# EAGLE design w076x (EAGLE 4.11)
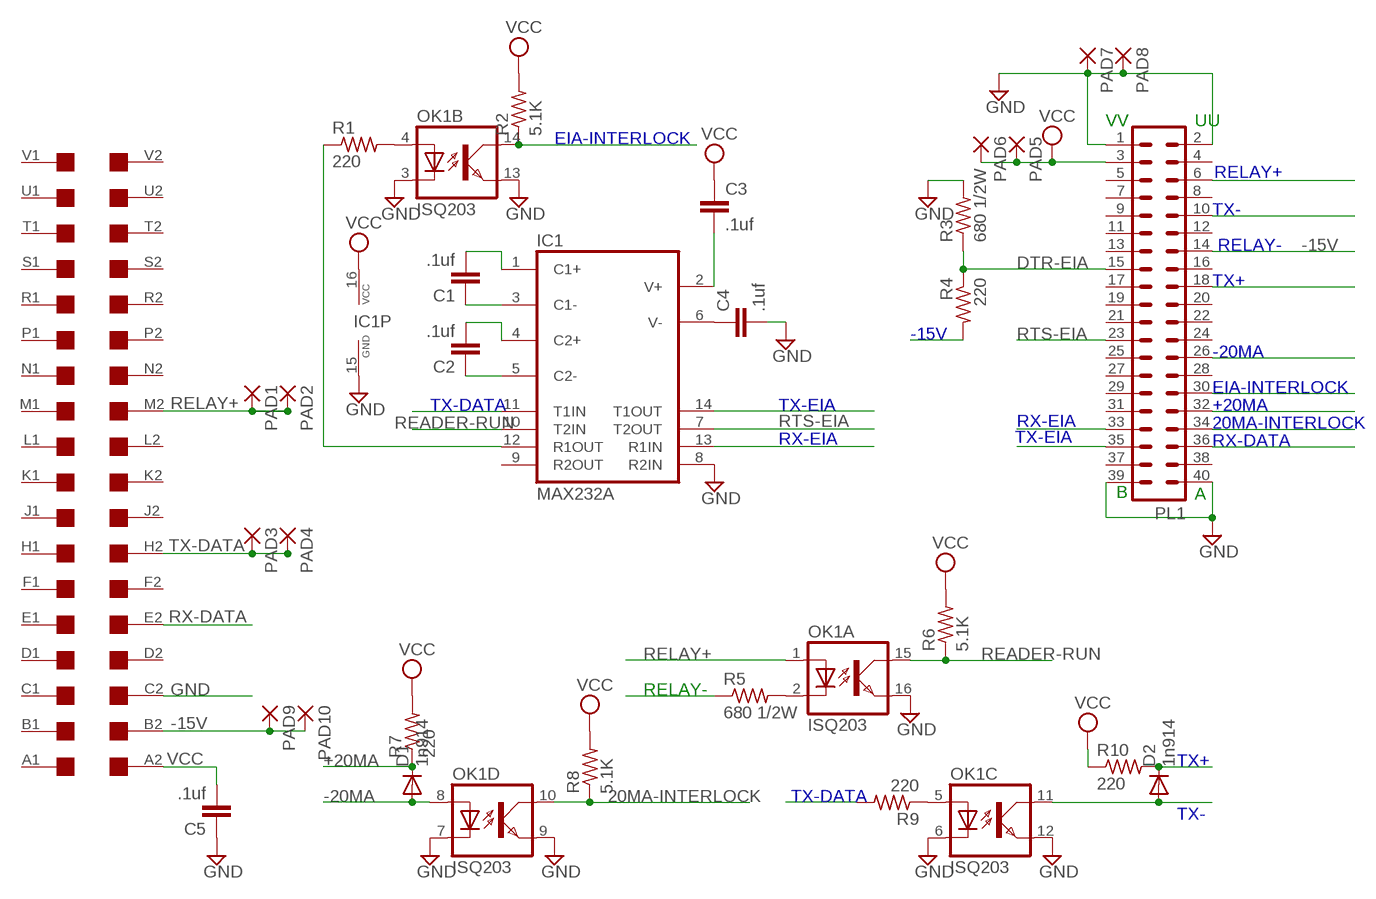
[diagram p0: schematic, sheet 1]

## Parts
C1  .1uf  C-EU050-025X075  [C050-025X075]
C2  .1uf  C-EU050-025X075  [C050-025X075]
C3  .1uf  C-EU050-025X075  [C050-025X075]
C4  .1uf  C-EU050-025X075  [C050-025X075]
C5  .1uf  C-EU050-025X075  [C050-025X075]
D1  1n914  1N4004  [DO41-10]
D2  1n914  1N4004  [DO41-10]
IC1  MAX232A  MAX232  [DIL16]
OK1  ISQ203  ILQ1  [DIL16]
PAD1  1,6/0,8  [1,6/0,8]
PAD2  1,6/0,8  [1,6/0,8]
PAD3  1,6/0,8  [1,6/0,8]
PAD4  1,6/0,8  [1,6/0,8]
PAD5  1,6/0,8  [1,6/0,8]
PAD6  1,6/0,8  [1,6/0,8]
PAD7  1,6/0,8  [1,6/0,8]
PAD8  1,6/0,8  [1,6/0,8]
PAD9  1,6/0,8  [1,6/0,8]
PAD10  1,6/0,8  [1,6/0,8]
PL1  40H  [40H]
R1  220  R-US_0207/10  [0207/10]
R2  5.1K  R-US_0207/10  [0207/10]
R3  680 1/2W  R-US_0207/12  [0207/12]
R4  220  R-US_0207/10  [0207/10]
R5  680 1/2W  R-US_0207/12  [0207/12]
R6  5.1K  R-US_0207/10  [0207/10]
R7  220  R-US_0207/10  [0207/10]
R8  5.1K  R-US_0207/10  [0207/10]
R9  220  R-US_0207/10  [0207/10]
R10  220  R-US_0207/10  [0207/10]
U$1  DEC-FLIPCHIP  [DEC-FLIPCHIP]

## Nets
20MA-INTERLOCK: OK1.10(D:COL) PL1.34 R8.1
+20MA: D1.C PL1.32 R7.1
-15V: PAD9.1(P) PAD10.1(P) PL1.14 R4.2 R5.1 U$1.B2
-20MA: D1.A OK1.8(D:A) PL1.26
DTR-EIA: PL1.15 R3.1 R4.1
EIA-INTERLOCK: OK1.14(B:COL) PL1.30 R2.1
GND: C4.2 C5.1 IC1.8(R2IN) IC1.15(GND) OK1.3(B:C) OK1.6(C:C) OK1.7(D:C) OK1.9(D:EMIT) OK1.12(C:EMIT) OK1.13(B:EMIT) OK1.16(A:EMIT) PAD7.1(P) PAD8.1(P) PL1.1 PL1.2 PL1.39 PL1.40 R3.2 U$1.C2
N$1: C2.1 IC1.5(C2-)
N$2: C2.2 IC1.4(C2+)
N$3: C1.2 IC1.1(C1+)
N$4: C1.1 IC1.3(C1-)
N$5: OK1.2(A:C) R5.2
N$8: IC1.12(R1OUT) R1.1
N$9: C3.2 IC1.2(V+)
N$10: C4.1 IC1.6(V-)
N$11: OK1.4(B:A) R1.2
N$15: OK1.5(C:A) R9.1
READER-RUN: IC1.10(T2IN) OK1.15(A:COL) R6.1
RELAY+: OK1.1(A:A) PAD1.1(P) PAD2.1(P) PL1.6 U$1.M2
RTS-EIA: IC1.7(T2OUT) PL1.23
RX-DATA: PL1.36 U$1.E2
RX-EIA: IC1.13(R1IN) PL1.33
TX+: D2.C PL1.18 R10.2
TX-: D2.A OK1.11(C:COL) PL1.10
TX-DATA: IC1.11(T1IN) PAD3.1(P) PAD4.1(P) R9.2 U$1.H2
TX-EIA: IC1.14(T1OUT) PL1.35
VCC: C3.1 C5.2 IC1.16(VCC) PAD5.1(P) PAD6.1(P) PL1.3 R2.2 R6.2 R7.2 R8.2 R10.1 U$1.A2
Unconnected: IC1.9(R2OUT) PL1.4 PL1.5 PL1.7 PL1.8 PL1.9 PL1.11 PL1.12 PL1.13 PL1.16 PL1.17 PL1.19 PL1.20 PL1.21 PL1.22 PL1.24 PL1.25 PL1.27 PL1.28 PL1.29 PL1.31 PL1.37 PL1.38 U$1.A1 U$1.B1 U$1.C1 U$1.D1 U$1.D2 U$1.E1 U$1.F1 U$1.F2 U$1.H1 U$1.J1 U$1.J2 U$1.K1 U$1.K2 U$1.L1 U$1.L2 U$1.M1 U$1.N1 U$1.N2 U$1.P1 U$1.P2 U$1.R1 U$1.R2 U$1.S1 U$1.S2 U$1.T1 U$1.T2 U$1.U1 U$1.U2 U$1.V1 U$1.V2

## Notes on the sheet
- VV | UU
- EIA-INTERLOCK
- RELAY+
- TX-
- RELAY-
- TX+
- -15V
- -20MA
- EIA-INTERLOCK
- TX-DATA | TX-EIA | +20MA
- RX-EIA | 20MA-INTERLOCK
- RX-EIA | TX-EIA | RX-DATA
- B | A
- RELAY-
- TX+
- TX-DATA
- TX-

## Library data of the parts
C1-C5 = rcl:C-EU: CAPACITOR, European symbol
D1 D2 = diode:1N4004: DIODE
IC1 = maxim:MAX232: RS232 TRANSEIVER
OK1 = optocoupler:ILQ1: SIEMENS OPTO COUPLER
PAD1-PAD10 = wirepad:1,6/0,8: THROUGH-HOLE PAD
PL1 = con-harting-h:40H: CONNECTOR
R1-R10 = rcl:R-US_: RESISTOR, American symbol
U$1 = con-dec:DEC-FLIPCHIP: DEC Flip-Chip single card fingers

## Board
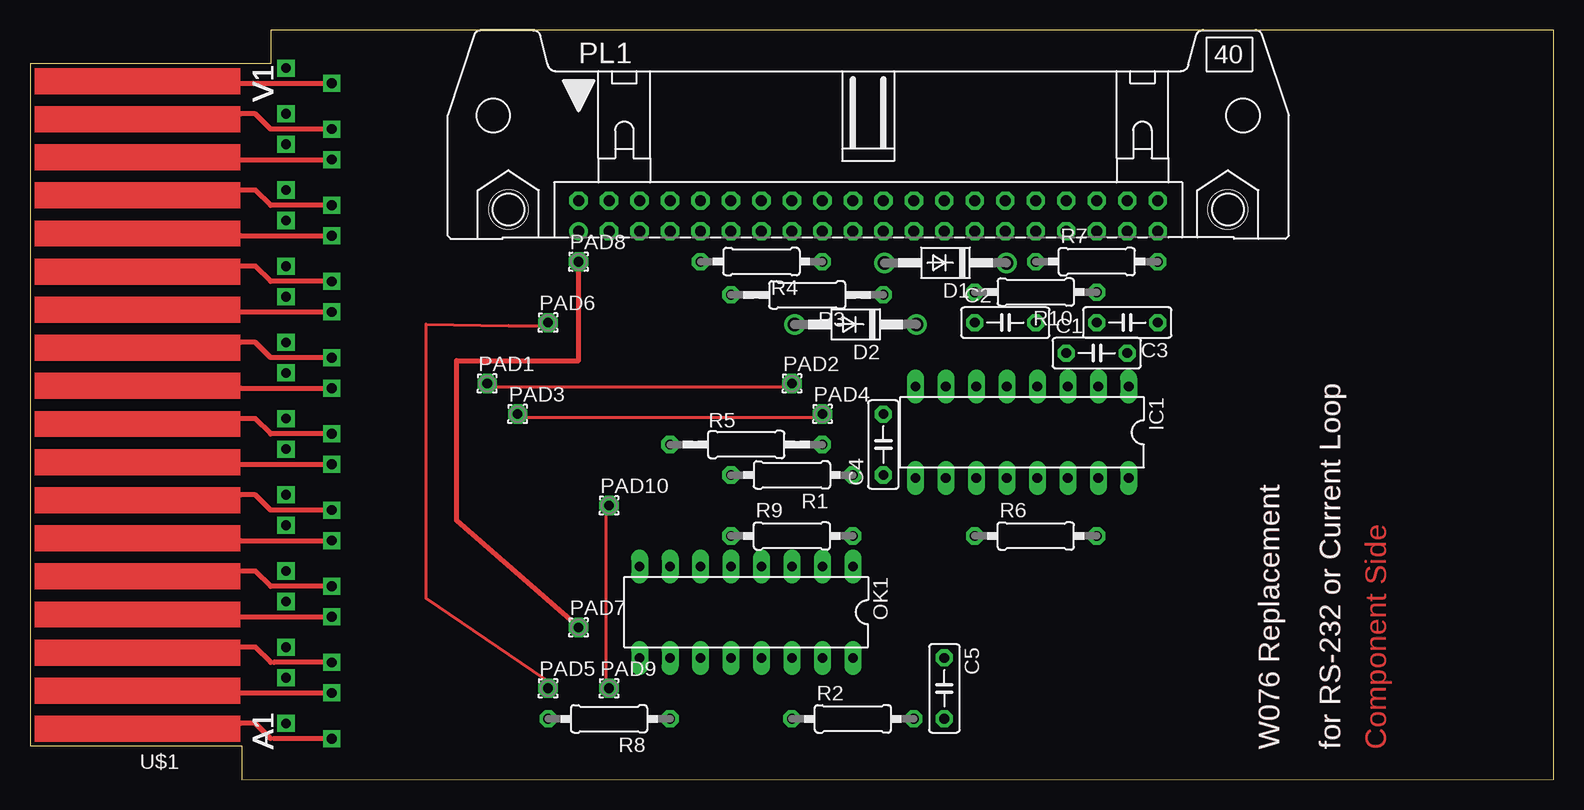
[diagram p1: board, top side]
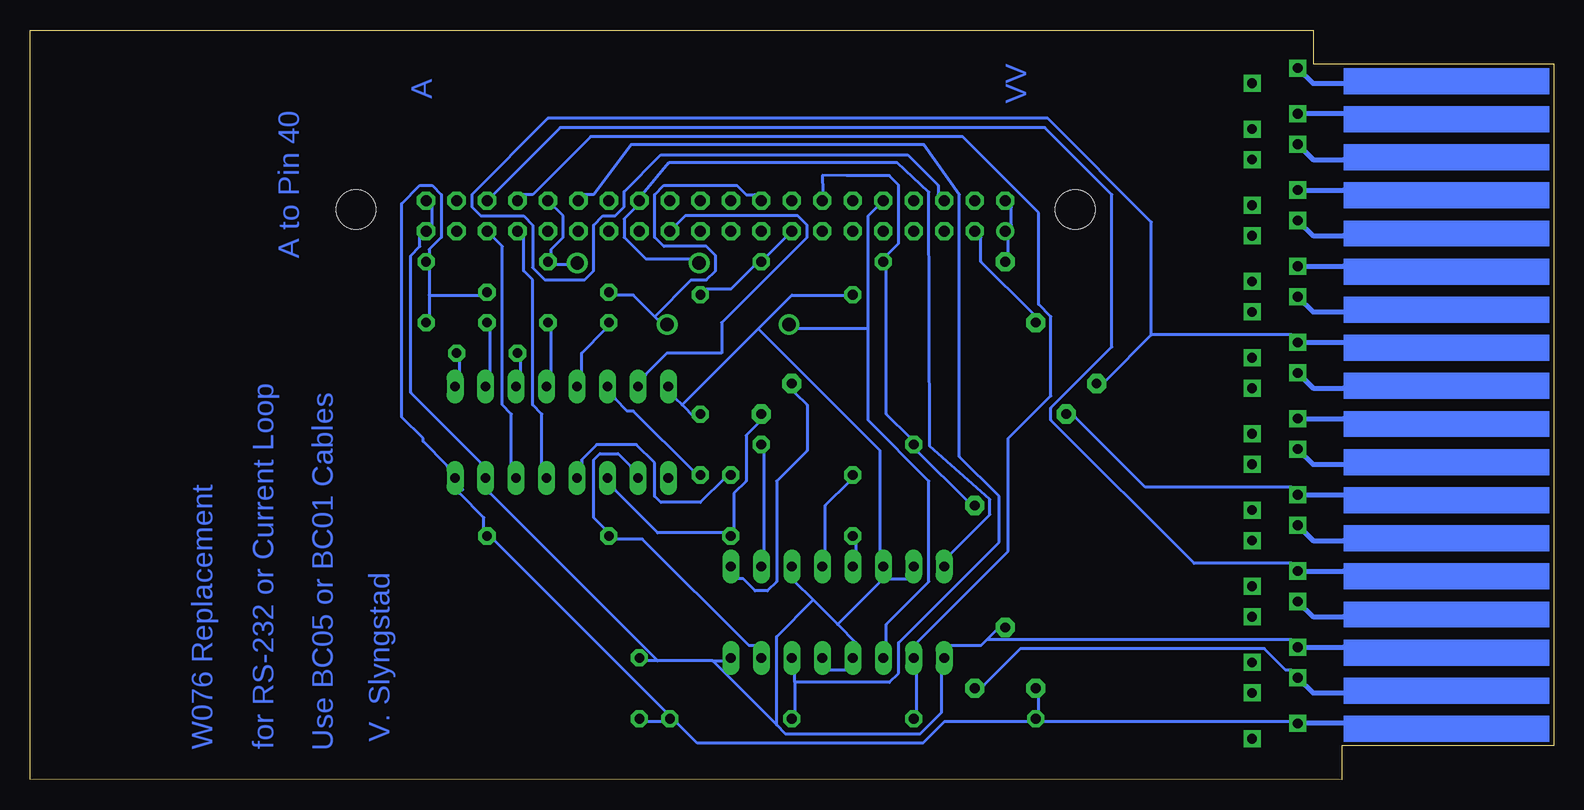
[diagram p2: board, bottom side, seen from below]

Size 126.98 x 62.48 mm. Coordinates in mm from the lower left corner, seen from the top.
Outline: 0,2.83 17.65,2.83 17.65,0 126.98,0.04 126.98,62.45 20.06,62.48 20.06,59.65 0,59.65 0,2.83
Copper layers (1*16): Top 0.035mm / dielectric 1.5mm / Bottom 0.035mm
Design rules "10mils": minimum track width 10mil, minimum drill 28mil, track to track 15mil, track to pad 10mil, pad to pad 10mil, via to via 10mil, smd to smd 10mil, copper to edge 40mil, drill to drill 10mil, minimum pad ring 12mil, minimum via ring 8mil, stop-mask expansion 0mil, vias tented up to drill 0mil, thermal gap 10mil

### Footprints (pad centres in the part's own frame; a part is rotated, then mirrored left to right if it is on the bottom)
C050-025X075 = drill 0.813 octagon: 1 -2.54,0; 2 2.54,0
DO41-10 = drill 1.118 round: A 5.08,0; C -5.08,0
DIL16 = drill 0.813 long: 1 -8.89,-3.81; 2 -6.35,-3.81; 3 -3.81,-3.81; 4 -1.27,-3.81; 5 1.27,-3.81; 6 3.81,-3.81; 7 6.35,-3.81; 8 8.89,-3.81; 9 8.89,3.81; 10 6.35,3.81; 11 3.81,3.81; 12 1.27,3.81; 13 -1.27,3.81; 14 -3.81,3.81; 15 -6.35,3.81; 16 -8.89,3.81
1,6/0,8 = drill 0.813 pad 1.6 octagon: 1 0,0
40H = drill 0.914 round: 1 -24.13,-1.27 | drill 0.914 octagon: 2 -24.13,1.27; 3 -21.59,-1.27; 4 -21.59,1.27; 5 -19.05,-1.27; 6 -19.05,1.27; 7 -16.51,-1.27; 8 -16.51,1.27; 9 -13.97,-1.27; 10 -13.97,1.27; 11 -11.43,-1.27; 12 -11.43,1.27; 13 -8.89,-1.27; 14 -8.89,1.27; 15 -6.35,-1.27; 16 -6.35,1.27; 17 -3.81,-1.27; 18 -3.81,1.27; 19 -1.27,-1.27; 20 -1.27,1.27; 21 1.27,-1.27; 22 1.27,1.27; 23 3.81,-1.27; 24 3.81,1.27; 25 6.35,-1.27; 26 6.35,1.27; 27 8.89,-1.27; 28 8.89,1.27; 29 11.43,-1.27; 30 11.43,1.27; 31 13.97,-1.27; 32 13.97,1.27; 33 16.51,-1.27; 34 16.51,1.27; 35 19.05,-1.27; 36 19.05,1.27; 37 21.59,-1.27; 38 21.59,1.27; 39 24.13,-1.27; 40 24.13,1.27 | hole 3.302: -29.972,0.533; 29.972,0.533
0207/10 = drill 0.813 octagon: 1 -5.08,0; 2 5.08,0
0207/12 = drill 0.813 octagon: 1 -6.35,0; 2 6.35,0
DEC-FLIPCHIP = drill 0.813 square: A1 -7.62,27.94; A2 -3.81,26.67; B1 -7.62,24.13; B2 -3.81,22.86; C1 -7.62,21.59; C2 -3.81,20.32; D1 -7.62,17.78; D2 -3.81,16.51; E1 -7.62,15.24; E2 -3.81,13.97; F1 -7.62,11.43; F2 -3.81,10.16; H1 -7.62,8.89; H2 -3.81,7.62; J1 -7.62,5.08; J2 -3.81,3.81; K1 -7.62,2.54; K2 -3.81,1.27; L1 -7.62,-1.27; L2 -3.81,-2.54; M1 -7.62,-3.81; M2 -3.81,-5.08; N1 -7.62,-7.62; N2 -3.81,-8.89; P1 -7.62,-10.16; P2 -3.81,-11.43; R1 -7.62,-13.97; R2 -3.81,-15.24; S1 -7.62,-16.51; S2 -3.81,-17.78; T1 -7.62,-20.32; T2 -3.81,-21.59; U1 -7.62,-22.86; U2 -3.81,-24.13; V1 -7.62,-26.67; V2 -3.81,-27.94

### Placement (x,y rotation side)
C1  88.9,35.56 0 top
C2  81.28,38.1 0 top
C3  91.44,38.1 180 top
C4  71.12,27.94 90 top
C5  76.2,7.62 270 top
D1  76.3,43.08 180 top
D2  68.8,37.95 180 top
IC1  82.67,28.96 180 top
OK1  59.68,13.97 180 top
PAD1  38.09,33.02 0 top
PAD2  63.49,33.02 0 top
PAD3  40.63,30.48 0 top
PAD4  66.04,30.48 0 top
PAD5  43.17,7.62 0 top
PAD6  43.17,38.1 0 top
PAD7  45.71,12.7 0 top
PAD8  45.71,43.18 0 top
PAD9  48.25,7.62 0 top
PAD10  48.25,22.86 0 top
PL1  69.84,46.99 0 top
R1  63.49,25.4 180 top
R2  68.58,5.08 0 top
R3  64.77,40.41 180 top
R4  60.95,43.18 180 top
R5  59.68,27.94 0 top
R6  83.81,20.32 0 top
R7  88.9,43.18 0 top
R8  48.25,5.08 180 top
R9  63.49,20.32 0 top
R10  83.81,40.64 180 top
U$1  17.52,31.37 180 top

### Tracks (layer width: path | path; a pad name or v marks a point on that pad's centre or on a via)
20MA-INTERLOCK
  Bottom 0.254: R8.1 53.08,5.59 53.08,8.89 OK1.10 53.08,11.43 45.46,19.05 45.46,28.45 41.9,32 41.9,38.61 42.92,39.62 42.92,47.24 49.27,53.59 80.26,53.59 85.09,48.77 85.85,48.77 PL1.34
+20MA
  Bottom 0.254: PL1.32 82.55,46.99 82.55,45.21 83.56,44.2 83.56,43.69 R7.1 83.31,42.93 82.04,42.93 D1.C
-15V
  Top 0.254: PAD9.1 48,8.38 48,22.1 PAD10.1
  Bottom 0.254: PAD10.1 48.76,23.11 53.08,27.43 R5.1 53.59,28.45 55.62,30.48 55.62,42.67 R4.2 55.62,43.69 54.6,44.7 54.6,49.55 55.37,50.32 55.37,50.34 58.92,50.34 60.95,50.37 60.9,49 PL1.14 | U$1.B2 21.84,9.14 22.35,9.14 24.12,10.92 44.45,10.92 47.49,7.87 PAD9.1
-20MA
  Bottom 0.254: OK1.8 50.29,18.8 46.98,22.1 46.98,23.37 52.01,27.81 52.06,48.97 54.71,51.41 73.73,51.41 75.94,48.77 PL1.26 76.45,47.75 77.47,46.74 77.47,45.21 75.69,43.43 71.88,43.43 D1.A
DTR-EIA
  Bottom 0.254: PL1.15 R4.1 66.54,42.93 68.58,40.89 70.61,40.89 R3.1
EIA-INTERLOCK
  Bottom 0.254: 63.24,8.13 63.24,8.89 OK1.14 | 63.24,8.13 63.24,5.59 R2.1 | 63.24,8.13 55.37,8.13 54.6,8.89 54.6,11.43 46.22,19.81 46.22,23.62 49.52,26.92 49.52,48.77 52.5,52.93 76.88,52.93 80.01,48.77 80.77,48.77 PL1.30
GND
  Top 0.406: PAD8.1 45.71,34.92 35.55,34.92 35.55,21.59 PAD7.1
  Bottom 0.254: 70.61,30.23 C4.2 71.62,30.23 72.64,31.24 | 72.64,31.24 73.15,31.75 IC1.8 | OK1.7 53.84,16.76 55.37,16.76 OK1.6 | OK1.13 60.45,9.14 58.92,9.14 OK1.12 58.16,11.43 59.68,12.95 | 61.72,14.99 59.68,12.95 | 61.72,14.99 63.24,16.51 OK1.3 | 59.68,12.95 56.13,16.51 OK1.6 | OK1.6 56.13,19.05 56.13,27.43 66.29,37.59 | 47.24,11.68 46.48,12.45 PAD7.1 | 47.24,11.68 47.75,11.18 50.29,11.18 OK1.9 51.05,8.89 51.05,5.59 52.83,3.81 64,3.81 64.77,4.57 | 47.24,11.68 21.84,11.68 U$1.C2 | PL1.40 93.47,47.75 93.47,46.23 PL1.39 94.48,45.21 94.48,44.45 95.25,43.69 95.25,32.26 89.4,26.42 IC1.15 88.64,23.88 74.67,9.91 | 74.67,9.91 75.69,9.91 C5.1 | 70.1,9.91 74.67,9.91 | 70.1,9.91 69.08,9.91 OK1.16 | 64.77,4.57 70.1,9.91 | 61.72,14.99 64.77,11.94 64.77,4.57 | PAD8.1 45.46,43.94 45.46,45.21 PL1.1 45.21,46.23 45.21,47.75 PL1.2 | 66.29,37.59 72.64,31.24 | 66.29,37.59 63.49,40.39 58.92,40.39 R3.2
N$1
  Bottom 0.254: IC1.5 81.02,34.04 81.02,35.56 78.99,37.59 C2.1
N$2
  Bottom 0.254: IC1.4 83.56,34.04 83.56,37.59 C2.2
N$3
  Bottom 0.254: IC1.1 91.18,34.04 91.18,35.05 C1.2
N$4
  Bottom 0.254: IC1.3 86.1,34.04 86.1,35.05 C1.1
N$5
  Bottom 0.254: OK1.2 65.78,19.05 65.78,27.43 R5.2
N$8
  Bottom 0.254: IC1.12 81.02,26.42 81.02,26.67 79.75,27.94 76.45,27.94 74.93,26.42 74.93,23.62 74.42,23.11 71.12,23.11 69.08,25.15 R1.1
N$9
  Bottom 0.254: IC1.2 88.64,34.04 88.64,37.59 C3.2
N$10
  Bottom 0.254: C4.1 71.62,25.65 76.7,30.73 77.21,30.73 78.23,31.75 IC1.6
N$11
  Bottom 0.254: OK1.4 60.7,19.05 60.7,22.86 58.67,24.89 R1.2
N$15
  Bottom 0.254: OK1.5 58.16,19.05 58.16,19.81 R9.1
READER-RUN
  Bottom 0.254: OK1.15 66.54,11.18 67.05,11.18 75.94,20.07 78.23,20.07 R6.1 | IC1.10 76.96,26.16 77.97,27.18 79.5,27.18 80.01,26.67 80.01,21.84 78.99,20.83 R6.1 | R6.1 78.48,19.81
RELAY+
  Top 0.254: PAD1.1 38.86,32.77 62.73,32.77 PAD2.1
  Bottom 0.254: OK1.1 68.07,16.76 67.56,16.76 66.54,15.75 65.53,15.75 64.77,16.51 64.77,24.89 62.22,27.43 62.22,31.24 63.24,32.26 PAD2.1 | 33.52,37.08 21.84,37.08 U$1.M2 | 33.52,37.08 37.33,33.27 PAD1.1 | 33.52,37.08 33.52,46.48 42.16,55.12 83.81,55.12 90.17,48.77 90.17,47.75 89.4,46.99 85.85,46.99 85.09,46.23 85.09,42.67 84.07,41.66 80.77,41.66 80.01,42.42 80.01,46.23 79.24,46.99 78.23,46.99 77.47,47.75 77.47,49.02 74.42,52.07 53.84,52.07 51.3,49.53 51.3,48.77 PL1.6
RTS-EIA
  Bottom 0.254: IC1.7 75.69,33.78 73.91,35.56 69.34,35.56 69.34,38.1 62.22,45.21 62.22,46.23 62.99,46.99 72.39,46.99 PL1.23
RX-DATA
  Bottom 0.254: U$1.E2 21.84,18.03 29.97,18.03 41.9,29.97 41.9,30.99 36.82,36.07 36.82,48.77 42.41,54.36 82.8,54.36 PL1.36
RX-EIA
  Bottom 0.254: IC1.13 84.32,26.42 84.32,30.48 85.09,31.24 85.09,41.66 85.85,42.42 85.85,45.21 PL1.33
TX+
  Bottom 0.254: 74.93,38.61 74.67,38.35 D2.C | 74.93,38.61 76.7,40.39 78.23,40.39 R10.2 | 74.93,38.61 71.88,41.66 70.61,41.66 69.84,42.42 69.84,43.69 70.61,44.45 74.16,44.45 74.93,45.21 74.93,48.77 74.16,49.53 68.07,49.53 67.31,48.77 66.54,48.77 PL1.18
TX-
  Bottom 0.254: 57.14,37.59 57.14,29.97 52.06,24.89 52.06,16.51 55.62,12.95 55.62,11.43 OK1.11 | 57.14,37.59 57.14,46.99 PL1.10 | 57.14,37.59 62.99,37.59 D2.A
TX-DATA
  Top 0.254: PAD4.1 65.27,30.23 41.4,30.23 PAD3.1
  Bottom 0.254: IC1.11 78.23,24.13 74.67,20.57 69.08,20.57 R9.2 68.32,20.83 68.32,23.88 67.31,24.89 67.31,28.7 66.29,29.72 PAD4.1 | U$1.H2 21.84,24.38 34.03,24.38 39.87,30.23 PAD3.1
TX-EIA
  Bottom 0.254: IC1.14 86.86,26.42 86.86,30.48 87.62,31.24 87.62,44.45 PL1.35
VCC
  Top 0.254: PAD6.1 42.41,37.85 39.87,37.85 33.02,37.97 33.02,15.11 42.92,8.38 PAD5.1
  Bottom 0.254: U$1.A2 21.84,4.83 42.67,4.83 R8.2 | R8.2 42.92,5.59 42.92,6.86 PAD5.1 | 93.72,40.39 93.72,42.67 R7.2 93.72,43.69 93.72,44.2 92.7,45.21 92.7,48.77 93.47,49.53 94.48,49.53 96.01,48.01 96.01,30.23 94.23,28.45 94.23,28.19 92.2,26.16 IC1.16 | 93.72,40.39 93.72,38.61 C3.1 | 93.72,40.39 89.4,40.39 R10.1 | R2.2 74.16,4.83 75.69,4.83 C5.2 | IC1.16 90.93,24.13 | R8.2 43.68,4.83 50.79,4.83 52.57,3.05 71.37,3.05 73.15,4.83 R2.2 | PL1.3 47.75,45.21 47.75,43.18 43.43,38.86 PAD6.1 | IC1.16 91.18,23.88 89.15,21.84 89.15,20.83 R6.2 88.39,20.07 73.91,5.59 R2.2

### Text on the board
Top: W076 Replacement | for RS-232 or Current Loop | Component Side
Bottom: VV | A | A to Pin 40 | V. Slyngstad | for RS-232 or Current Loop | W076 Replacement | Use BC05 or BC01 Cables
tPlace: W076 Replacement | for RS-232 or Current Loop
tNames: V1 | V1 | V1 | V1 | V1 | V1 | V1 | V1 | V1 | V1 | V1 | V1 | V1 | V1 | V1 | V1 | V1 | V1 | V1 | V1 | V1 | V1 | V1 | V1 | V1 | V1 | V1 | V1 | V1 | V1 | V1 | V1 | A1 | A1 | A1 | A1 | A1 | A1 | A1 | A1 | A1 | A1 | A1 | A1 | A1 | A1 | A1 | A1 | A1 | A1 | A1 | A1 | A1 | A1 | A1 | A1 | A1 | A1 | A1 | A1 | A1 | A1 | A1 | A1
